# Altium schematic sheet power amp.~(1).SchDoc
size A3
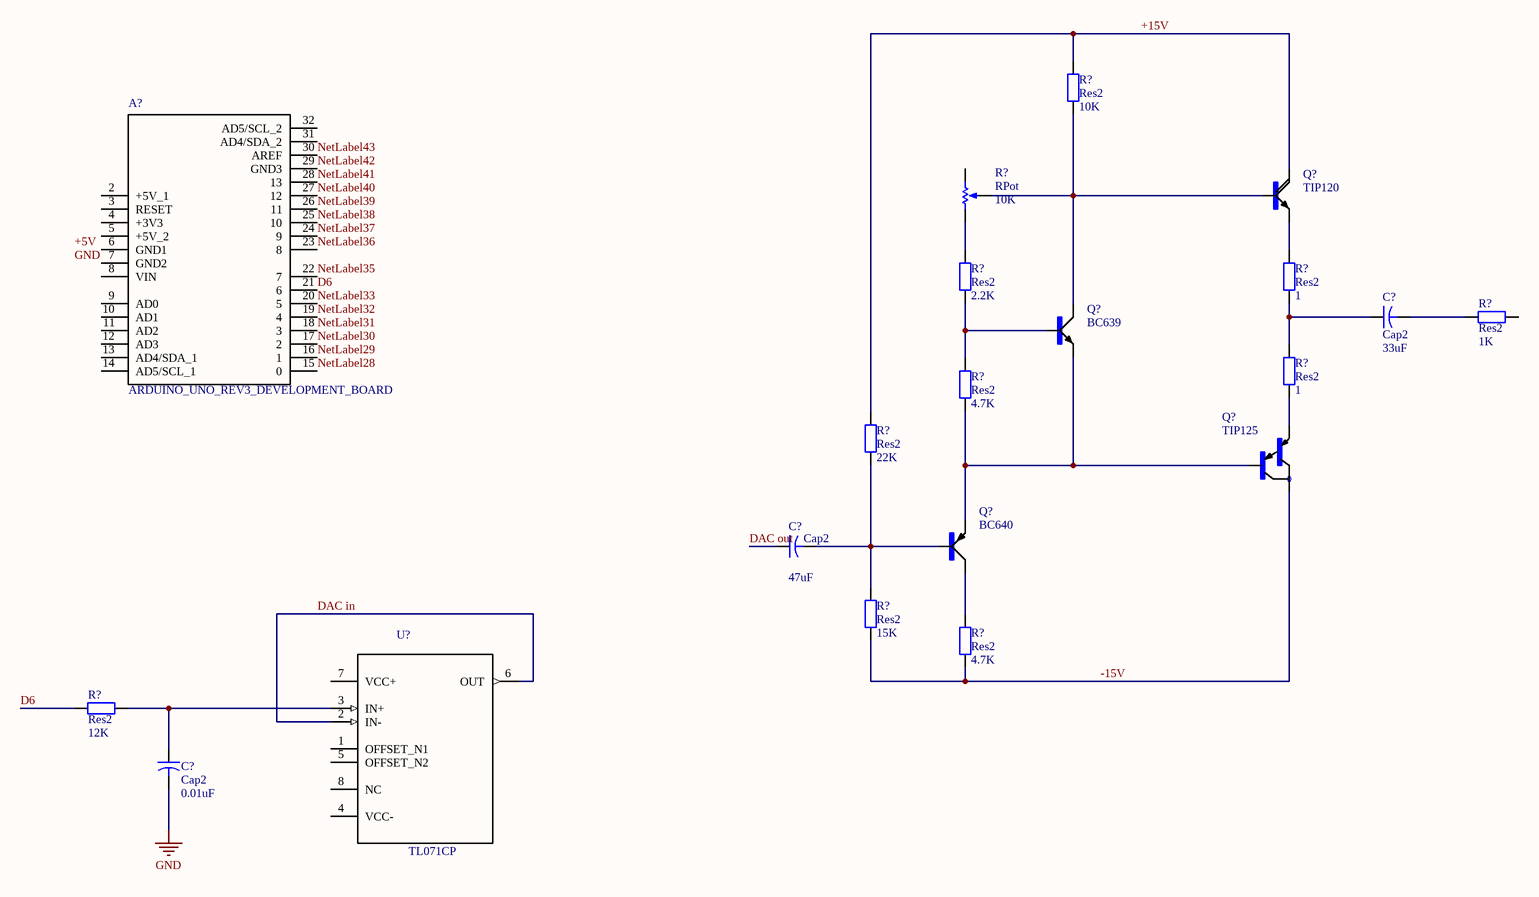
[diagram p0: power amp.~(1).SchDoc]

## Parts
(Parts that share a designator on the sheet are numbered #1, #2 ... from top to bottom, then left to right.)
A?  ARDUINO_UNO_REV3_DEVELOPMENT_BOARD  [*ARDUINO_UNO_REV3_DEVELOPMENT_BOARD]
C?#1  Cap2  value 33uF  [CAPR5-4X5]
C?#2  Cap2  value 47uF  [CAPR5-4X5]
C?#3  Cap2  value 0.01uF  [CAPR5-4X5]
Q?#1  TIP120  [*TO220AH_TIP120(Primary)]
Q?#2  BC639  [*SOT54D_BC639(Primary)]
Q?#3  TIP125  [*TO220]
Q?#4  BC640  [*SOT54D_BC640(Primary)]
R?#1  Res2  value 10K  [AXIAL-0.4]
R?#2  RPot  value 10K  [VR5]
R?#3  Res2  value 2.2K  [AXIAL-0.4]
R?#4  Res2  value 1  [AXIAL-0.4]
R?#5  Res2  value 1K  [AXIAL-0.4]
R?#6  Res2  value 1  [AXIAL-0.4]
R?#7  Res2  value 4.7K  [AXIAL-0.4]
R?#8  Res2  value 22K  [AXIAL-0.4]
R?#9  Res2  value 15K  [AXIAL-0.4]
R?#10  Res2  value 4.7K  [AXIAL-0.4]
R?#11  Res2  value 12K  [AXIAL-0.4]
U?  TL071CP  [*DIP254P762X508-8]

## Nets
GND: C?#3.2
+15V: Q?#1.C R?#1.2 R?#8.2
-15V: Q?#3.2(C) R?#9.1 R?#10.1
D6: A?.21(6) R?#11.1
DAC in: U?.2(IN-) U?.6(OUT)
DAC out: C?#2.1
NetLabel28: A?.15(0)
NetLabel29: A?.16(1)
NetLabel30: A?.17(2)
NetLabel31: A?.18(3)
NetLabel32: A?.19(4)
NetLabel33: A?.20(5)
NetLabel35: A?.22(7)
NetLabel36: A?.23(8)
NetLabel37: A?.24(9)
NetLabel38: A?.25(10)
NetLabel39: A?.26(11)
NetLabel40: A?.27(12)
NetLabel41: A?.28(13)
NetLabel42: A?.29(GND3)
NetLabel43: A?.30(AREF)
NetC?#1_1: C?#1.1 R?#4.1 R?#6.2
NetC?#1_2: C?#1.2 R?#5.2
NetC?#2_2: C?#2.2 Q?#4.B R?#8.1 R?#9.2
NetC?#3_1: C?#3.1 R?#11.2 U?.3(IN+)
NetQ?#1_B: Q?#1.B Q?#2.C R?#1.1 R?#2.3(TAP)
NetQ?#1_E: Q?#1.E R?#4.2
NetQ?#2_B: Q?#2.B R?#3.1 R?#7.2
NetQ?#2_E: Q?#2.E Q?#3.1(B) Q?#4.E R?#7.1
NetQ?#3_3: Q?#3.3(E) R?#6.1
NetQ?#4_C: Q?#4.C R?#10.2
NetR?#2_1: R?#2.1(TOP) R?#3.2

Not connected (* = marked no-connect by the designer): A? 2(+5V_1) 3(RESET) 4(+3V3) 5(+5V_2) 6(GND1) 7(GND2) 8(VIN) 9(AD0) 10(AD1) 11(AD2) 12(AD3) 13(AD4/SDA_1) 14(AD5/SCL_1) 31(AD4/SDA_2) 32(AD5/SCL_2); R?#2 2(BOT); R?#5 1; U? 1(OFFSET_N1) 4(VCC-) 5(OFFSET_N2) 7(VCC+) 8(NC)

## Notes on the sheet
- Labels drawn without touching a wire or pin: +5V, GND

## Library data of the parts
A? = ARDUINO_UNO_REV3_DEVELOPMENT_BOARD: Plated Through Hole Protoboard Arduino Mega Platform Evaluation Expansion Board; MP: ARDUINO UNO REV3 DEVELOPMENT BOARD
C?#1-C?#3 = Cap2: Capacitor
Q?#1 = TIP120: Bipolar _BJT_ Transistor NPN - Darlington 60V 5A 2W Through Hole TO-220-3; MF: ON Semiconductor
Q?#2 = BC639: Bipolar _BJT_ Transistor NPN 80V 1A 200MHz 625mW Through Hole TO-92-3; MF: ON Semiconductor
Q?#3 = TIP125: Bipolar _BJT_ Transistor PNP - Darlington 60V 5A 2W Through Hole TO-220-3; MF: ON Semiconductor
Q?#4 = BC640: Bipolar _BJT_ Transistor PNP 80V 500mA 150MHz 625mW Through Hole TO-92-3; MF: ON Semiconductor
R?#1 R?#3-R?#11 = Res2: Resistor
R?#2 = RPot: Potentiometer; Sim Note: Enter the Resistance value and the set point into parameter fields.; Set Position: 0.5
U? = TL071CP: J-FET Amplifier 1 Circuit 8-PDIP; MF: Texas Instruments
